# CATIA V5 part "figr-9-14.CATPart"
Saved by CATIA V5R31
Part number: Part2
Bounding box of the stored display mesh (mm): x -33.329 to 47.777, y -126.495 to 121.369, z -47.545 to 64.906
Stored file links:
  D:\PROJECTS\Project 2021\US EDITION\CATIA V5 6R 2021\Resources\Part Files\c09_catia_v5_6r2021_prt\c09_catia_v5_6r2021_prt\figr-9-14.CATPart
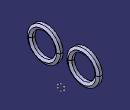
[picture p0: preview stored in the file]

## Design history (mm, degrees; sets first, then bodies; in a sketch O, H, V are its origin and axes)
Body1 (main body)
  Sketch1 on yz-plane, origin (0, 0, 0), H (0, 1, 0), V (0, 0, 1)
    circle A1 centre (-70.2613, 8.6726) radius 37.6716
    circle A2 centre (65.3061, 8.6726) radius 37.5
    radius A2 = 37.5
    radius A1 = 37.6716
  Plane1: type Angle, RefPlane yz-plane, Direction Sketch1.V, Angle 10
  Plane2: type Offset, RefPlane Plane1, Offset 55
  Sketch2 on Plane2, origin (44.5537, 64.0556, 0), H (-0.1736, 0.9848, 0), V (0, 0, 1)
    point P1 (-10.3597, -23.8575)
    point P2 (-2.157, -28.5933)
    point P3 (-2.157, -19.1216)
    point P4 (-10.3597, -14.3858)
    point P5 (-18.5625, -19.1216)
    point P6 (-18.5625, -28.5933)
    point P7 (-10.3597, -33.3292)
    point P8 (-2.157, -23.8575)
    line L1 (-2.157, -28.5933) -> (-2.157, -19.1216)
    line L2 (-2.157, -19.1216) -> (-10.3597, -14.3858)
    line L3 (-10.3597, -14.3858) -> (-18.5625, -19.1216)
    line L4 (-18.5625, -19.1216) -> (-18.5625, -28.5933)
    line L5 (-18.5625, -28.5933) -> (-10.3597, -33.3292)
    line L6 (-10.3597, -33.3292) -> (-2.157, -28.5933)
    construction line L7 (-10.3597, -23.8575) -> (-2.157, -23.8575)
    construction circle A1 centre (-10.3597, -23.8575) radius 9.4717
    construction arc A2 centre (-18.5625, -28.5933) radius 9.4717 from (-18.5625, -19.1216) to (-10.3597, -33.3292) cw
    construction arc A3 centre (-2.157, -19.1216) radius 9.4717 from (-10.3597, -14.3858) to (-2.157, -28.5933) ccw
    horizontal: L7 H
    coincidence: A1 P2, A1 P3, A1 P4, A1 P5, A1 P6, A1 P7, A2 P1, A3 P1
    midpoint: P8 L1
    parallelism: L1 L4
  Rib1: profile Sketch2, centre curve Sketch1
